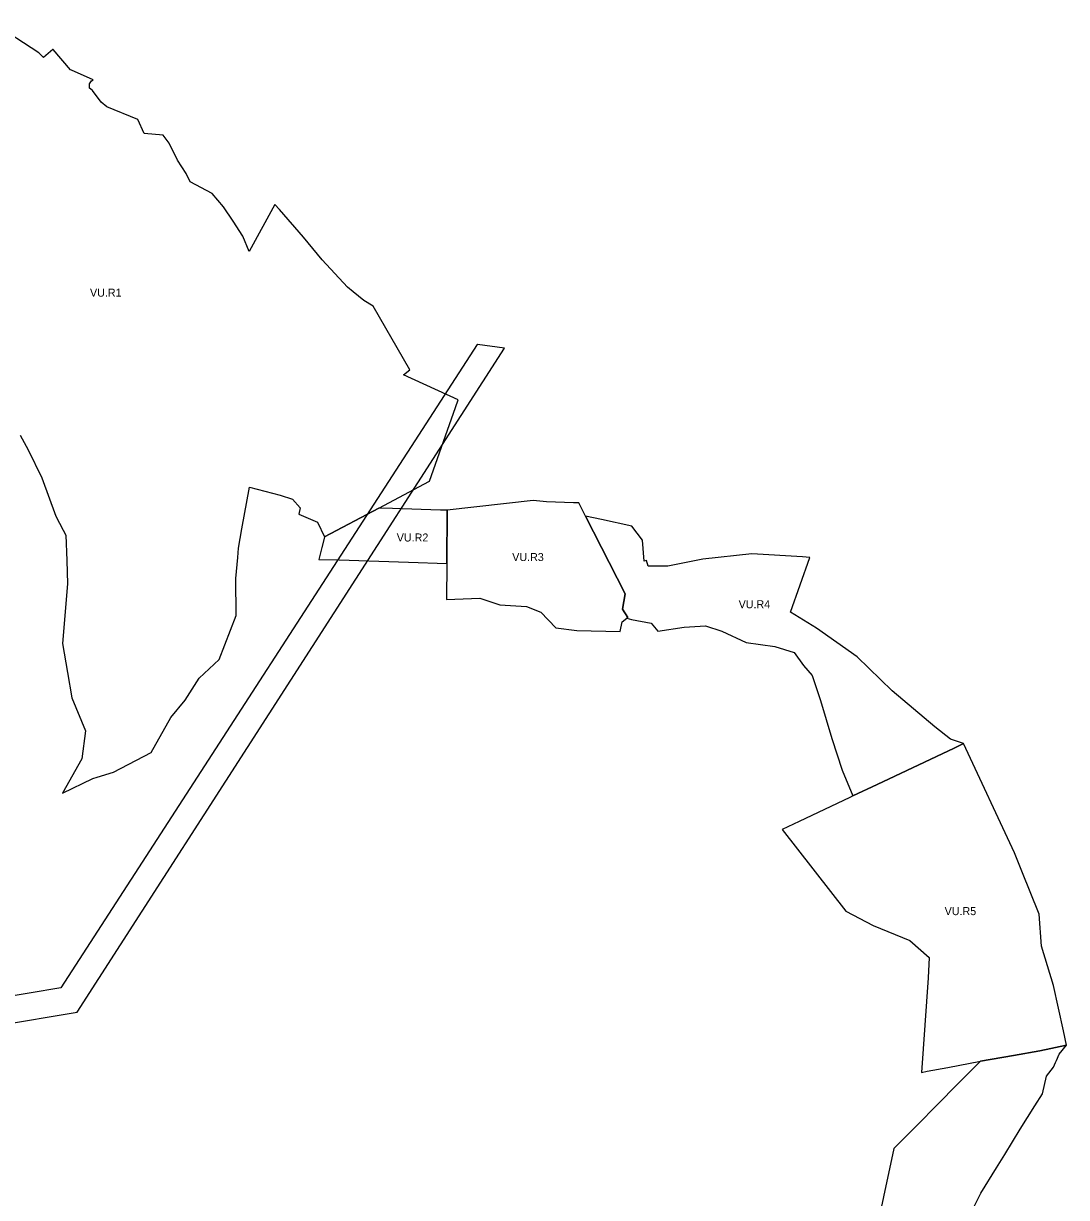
# Model space of a CAD drawing. Extents: x -439083 to -433688, y -1130252 to -1121189.
# Drawn here: x -435848 to -434285, y -1123234 to -1121474 of the extents above; entities that cross this region are included whole.
import ezdxf

# ---------------------------------------------------------------- set-up
doc = ezdxf.new("R2010")
doc.units = 0
for name, color, linetype in [('Vrstva 10', 7, 'Continuous'), ('Vrstva 28', 7, 'Continuous'), ('Vrstva 31', 7, 'Continuous')]:
    doc.layers.add(name, color=color, linetype=linetype)

msp = doc.modelspace()

# ---------------------------------------------------------------- linework, layer by layer
at = {"layer": 'Vrstva 10'}
for p, q in [((-435167.9, -1121954.9), (-435791.5, -1122919.4)), ((-435767.3, -1122955.9), (-435127, -1121960.4)), ((-435791.5, -1122919.4), (-437337.2, -1123177)), ((-437330.6, -1123216.5), (-435767.3, -1122955.9))]:
    msp.add_line(p, q, dxfattribs=at)
msp.add_lwpolyline([(-435127, -1121960.4), (-435167.3, -1121955), (-435167.9, -1121954.9)], dxfattribs=at)
at = {"layer": 'Vrstva 28'}
for p, q in [((-435239.3, -1122159.8), (-435200.2, -1122049.6)), ((-435315.3, -1122200.1), (-435239.3, -1122159.8)), ((-435396.7, -1122243.2), (-435315.3, -1122200.1)), ((-435212.6, -1122203.5), (-435213.4, -1122283.3)), ((-434946, -1122328.8), (-435005.4, -1122212.3)), ((-435005.4, -1122212.3), (-434946, -1122328.8)), ((-435400.4, -1122259.5), (-435404.9, -1122277.1)), ((-435404.9, -1122277.1), (-435374.3, -1122278)), ((-435374.3, -1122278), (-435270.6, -1122281.1)), ((-435270.6, -1122281.1), (-435213.4, -1122283.3)), ((-434946, -1122328.8), (-434949.7, -1122351.7)), ((-434949.7, -1122351.7), (-434941.8, -1122364.4)), ((-434941.8, -1122364.4), (-434943.2, -1122365.4)), ((-434438.8, -1122553.3), (-434458.6, -1122546.6)), ((-434452.8, -1122560), (-434438.8, -1122553.3)), ((-434438.8, -1122553.3), (-434452.8, -1122560)), ((-434452.8, -1122560), (-434568.1, -1122614.5)), ((-434363.9, -1123020.8), (-434324.5, -1123013.7)), ((-434324.5, -1123013.7), (-434363.9, -1123020.8)), ((-434324.5, -1123013.7), (-434284.6, -1123005.4)), ((-434413.4, -1123029.2), (-434447.2, -1123063.3)), ((-434413.4, -1123029.2), (-434363.9, -1123020.8)), ((-434363.9, -1123020.8), (-434413.4, -1123029.2))]:
    msp.add_line(p, q, dxfattribs=at)
for points in [[(-435200.2, -1122049.6), (-435196.2, -1122038), (-435278.1, -1122000.7), (-435268.7, -1121992.8), (-435323.4, -1121897.6), (-435337.5, -1121889), (-435353.6, -1121876), (-435361.9, -1121869), (-435399.8, -1121828.2), (-435428.2, -1121793.9), (-435463.7, -1121752.8), (-435471.1, -1121744.9), (-435509.5, -1121815.7), (-435518.9, -1121792.4), (-435533.2, -1121770.1), (-435548.1, -1121748.5), (-435564.8, -1121728.6), (-435597.9, -1121711.3), (-435603.8, -1121698.6), (-435616.9, -1121678.4), (-435629.4, -1121653.2), (-435638.3, -1121641.4), (-435666.7, -1121638.5), (-435676.2, -1121617.5), (-435722.6, -1121598.7), (-435731.4, -1121591.9), (-435744.2, -1121574.2), (-435746.8, -1121572.2), (-435748.9, -1121570.6), (-435748.6, -1121564.2), (-435745.9, -1121559.9), (-435743.3, -1121558.1), (-435775.6, -1121543.9), (-435777.3, -1121543.2), (-435803.3, -1121512.5), (-435803.5, -1121512.7), (-435817.5, -1121524.7), (-435824.6, -1121517.5), (-435892.7, -1121473.7)], [(-435852.8, -1122090.7), (-435840.6, -1122113.1), (-435820.2, -1122154.7), (-435798.9, -1122212.4), (-435788, -1122233.2), (-435784.1, -1122240.7), (-435782.5, -1122278.9), (-435781.5, -1122313.8), (-435789.1, -1122403.1), (-435781.6, -1122446.7), (-435775, -1122484.7), (-435754.9, -1122534.2), (-435760.2, -1122575.9), (-435789.3, -1122627.6), (-435743.8, -1122605.4), (-435737.3, -1122603.5), (-435712.5, -1122595.9), (-435656.4, -1122566.8), (-435626.7, -1122514.2), (-435605.3, -1122488.1), (-435584.5, -1122455.2), (-435554.4, -1122427.3), (-435528.8, -1122361.1), (-435529.4, -1122305.7), (-435526.6, -1122274.4), (-435525.2, -1122260.2), (-435520.6, -1122231.2), (-435508.7, -1122168.7), (-435463.1, -1122181), (-435444.3, -1122186.8), (-435433.2, -1122199.6), (-435435, -1122209.2), (-435406.8, -1122221.3), (-435396.7, -1122243.2)], [(-435005.4, -1122212.3), (-435015.5, -1122192.5), (-435023.4, -1122192.2), (-435063.6, -1122191), (-435083.9, -1122188.7), (-435212.6, -1122203.5)], [(-435213.4, -1122283.3), (-435212.6, -1122203.5), (-435222.6, -1122203.2), (-435294.8, -1122200.8), (-435315.3, -1122200.1), (-435396.7, -1122243.2)], [(-434458.6, -1122546.6), (-434482, -1122528.2), (-434545.8, -1122474.4), (-434598.2, -1122423.4), (-434659.1, -1122380.1), (-434698.1, -1122356.1), (-434669.2, -1122274.3), (-434680.1, -1122273.4), (-434756.1, -1122268.8), (-434829.6, -1122276.7), (-434881.8, -1122287.3), (-434911.6, -1122287.3), (-434914.2, -1122278.9), (-434917.3, -1122279.9), (-434920.2, -1122248.5), (-434936, -1122227.5), (-434981.6, -1122217.5), (-435005.4, -1122212.3)], [(-435396.7, -1122243.2), (-435396.3, -1122244), (-435400.4, -1122259.5)], [(-435213.4, -1122283.3), (-435213.4, -1122283.6), (-435213.9, -1122337.2), (-435163.5, -1122335.2), (-435133.7, -1122345.1), (-435094, -1122347.9), (-435072.2, -1122356.2), (-435050, -1122379.6), (-435018.2, -1122383.6), (-434953.4, -1122385.1), (-434950.3, -1122370.5), (-434943.2, -1122365.4), (-434941.8, -1122364.4)], [(-434941.8, -1122364.4), (-434949.7, -1122351.7), (-434946, -1122328.8)], [(-434943.2, -1122365.4), (-434936.7, -1122367.3), (-434907, -1122372.6), (-434897, -1122384.5), (-434857.3, -1122378.6), (-434825.6, -1122376.6), (-434801.1, -1122384.5), (-434764.7, -1122401.7), (-434721.7, -1122407.7), (-434692.6, -1122416.9), (-434678.7, -1122436.1), (-434665.5, -1122451.3), (-434653, -1122488.5), (-434636.1, -1122545.4), (-434620.7, -1122593.2), (-434604.8, -1122631.8)], [(-434284.6, -1123005.4), (-434289.2, -1122983.9), (-434303.9, -1122915.8), (-434322.1, -1122857.1), (-434325.8, -1122808.8), (-434351.6, -1122744.4), (-434362.6, -1122716.9), (-434438.8, -1122553.3)], [(-434604.8, -1122631.8), (-434568.1, -1122614.5), (-434452.8, -1122560)], [(-434568.1, -1122614.5), (-434604.8, -1122631.8), (-434609.2, -1122633.9), (-434685, -1122669.8), (-434710.7, -1122681.8), (-434615.2, -1122804.5), (-434574.1, -1122825.8), (-434519.6, -1122848.5), (-434490.5, -1122874), (-434491.7, -1122904.5), (-434501.9, -1123046.1), (-434493.4, -1123044.5), (-434462.6, -1123038.6), (-434413.4, -1123029.2)], [(-434518, -1123539.7), (-434512.4, -1123493.4), (-434478.2, -1123431.2), (-434471.9, -1123405.2), (-434458.9, -1123351.3), (-434449.8, -1123301), (-434412.9, -1123227.4), (-434389.6, -1123189.4), (-434377.2, -1123169.1), (-434354, -1123131.2), (-434332, -1123096.3), (-434320.8, -1123078.5), (-434314.4, -1123051.7), (-434304.3, -1123038.5), (-434301.1, -1123031.3), (-434299.7, -1123028.1), (-434295.7, -1123018.7), (-434284.6, -1123005.4), (-434324.5, -1123013.7)], [(-434447.2, -1123063.3), (-434478.5, -1123094.9), (-434507.9, -1123124.6), (-434543.2, -1123160.2), (-434606.8, -1123457.2), (-434580.6, -1123591.5)]]:
    msp.add_lwpolyline(points, dxfattribs=at)

# ---------------------------------------------------------------- texts
at = {"layer": 'Vrstva 31'}
for s, p in [('VU.R1', (-435747.9, -1121883.3)), ('VU.R2', (-435288.2, -1122250.3)), ('VU.R3', (-435115.2, -1122279.6)), ('VU.R4', (-434775.9, -1122350.4)), ('VU.R5', (-434467.2, -1122810.4))]:
    msp.add_text(s, height=12, dxfattribs=at).set_placement(p)

doc.saveas('drawing.dxf')
